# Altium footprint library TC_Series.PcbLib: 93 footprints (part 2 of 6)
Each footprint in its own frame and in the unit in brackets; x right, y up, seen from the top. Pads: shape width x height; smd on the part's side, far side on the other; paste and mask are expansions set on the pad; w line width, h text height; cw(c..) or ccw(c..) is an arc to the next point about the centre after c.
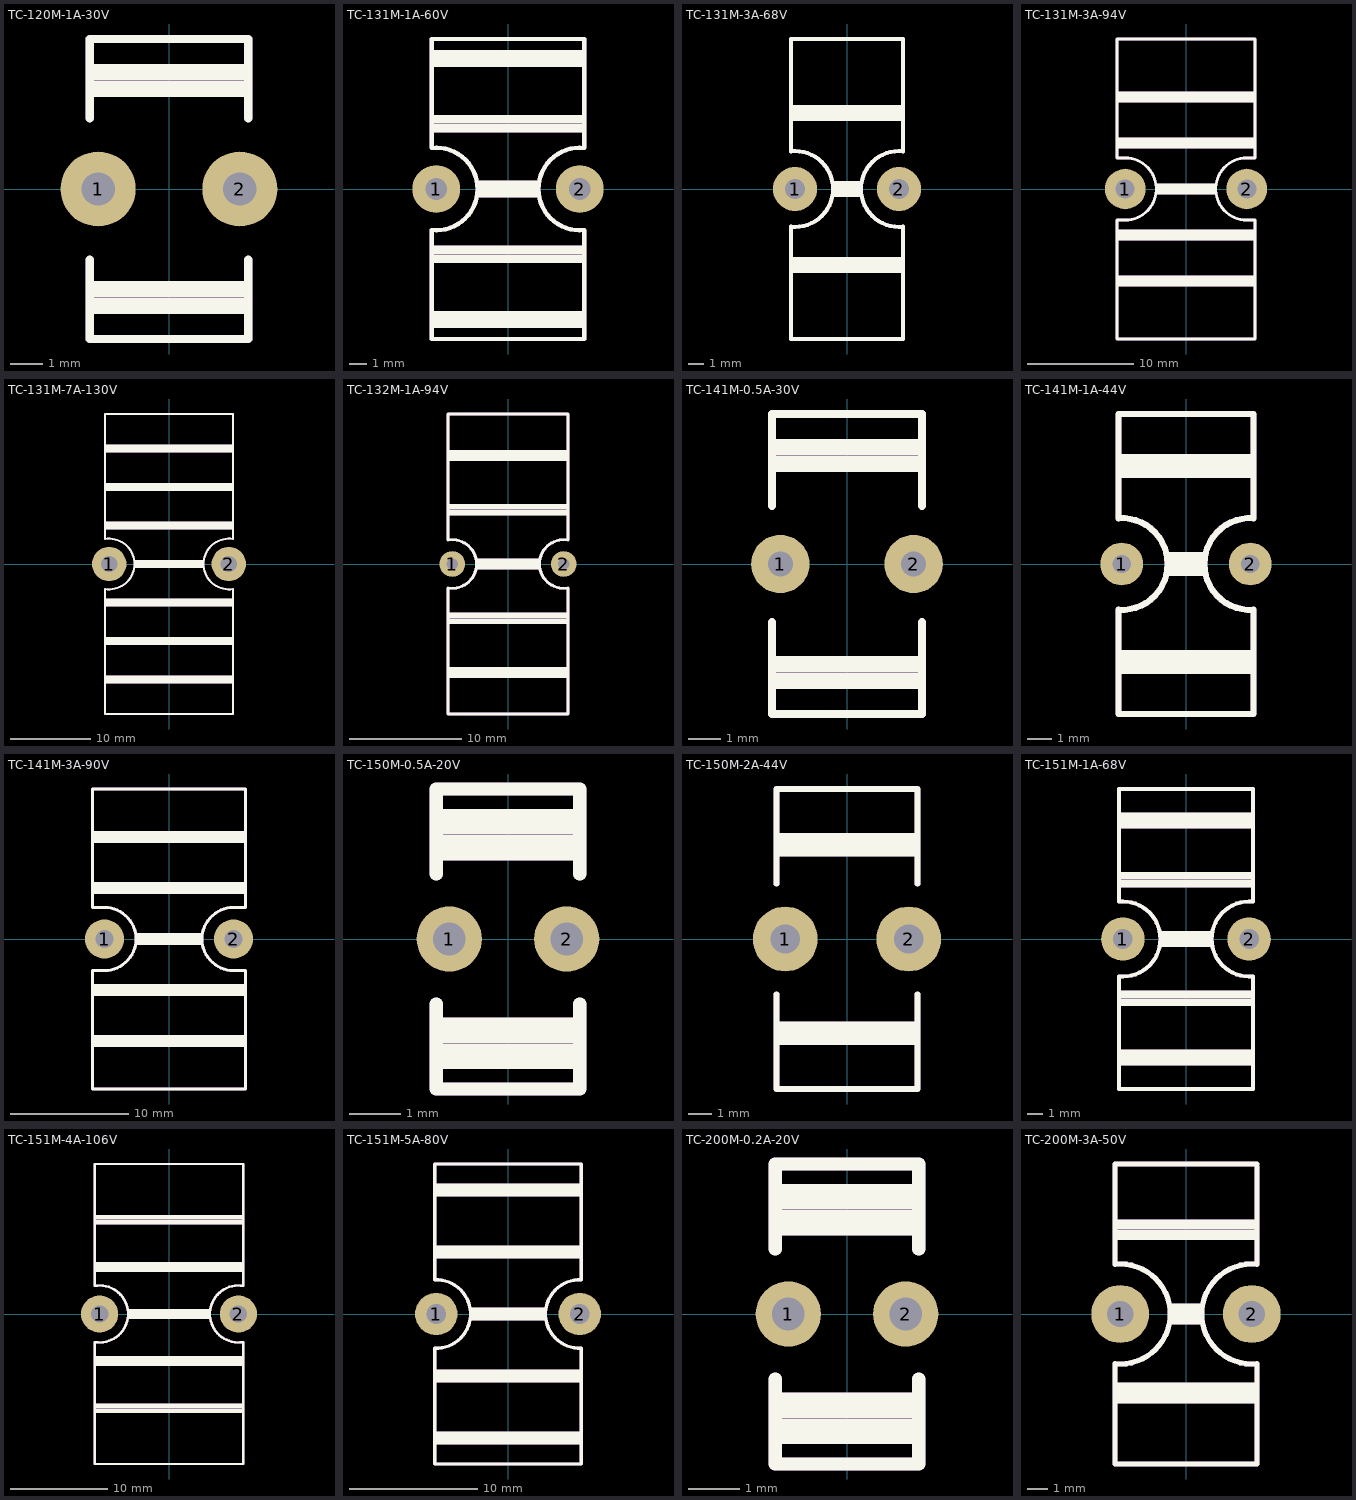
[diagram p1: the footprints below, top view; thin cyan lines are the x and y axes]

## TC-120M-1A-30V [mil]
pads (2):
  round 90 hole 40: 1(-85,0) 2(85,0)
Top Overlay:
  lines w10: -95,-85 -95,-180 95,-180 95,-85 ; -95,85 -95,180 95,180 95,85
  lines w19.68: -90,-140 90,-140 ; -90,-120 90,-120 ; -90,120 90,120 ; -90,140 90,140
Mechanical 29:
  lines w10: -95,-85 -95,-180 95,-180 95,-85 ; -95,85 -95,180 95,180 95,85
  lines w19.68: -90,-140 90,-140 ; -90,-120 90,-120 ; -90,120 90,120 ; -90,140 90,140
  text "'.Designator'" at -800,-62.45 h200

## TC-131M-1A-60V [mil]
pads (2):
  round 110 hole 50: 1(-165,0) 2(165,0)
Top Overlay:
  lines w10: -175,-94.48 -175,-345 175,-345 175,-95 ; -175,-94.47 ccw(c-165,0) -174.95,94.48 ; -175,94.48 -175,345 175,345 175,95 ; 174.95,-94.48 cw(c165,0) 174.93,94.48
  lines w19.68: -170,-310 170,-310 ; -170,-290 170,-290 ; -170,-160 170,-160 ; -170,-140 170,-140 ; -170,140 170,140 ; -170,160 170,160 ; -170,290 170,290 ; -170,310 170,310 ; -65,-10 65,-10 ; -65,10 65,10
Mechanical 29:
  lines w10: -175,-94.48 -175,-345 175,-345 175,-95 ; -175,-94.47 ccw(c-165,0) -174.95,94.48 ; -175,94.48 -175,345 175,345 175,95 ; 174.95,-94.48 cw(c165,0) 174.93,94.48
  lines w19.68: -170,-310 170,-310 ; -170,-290 170,-290 ; -170,-160 170,-160 ; -170,-140 170,-140 ; -170,140 170,140 ; -170,160 170,160 ; -170,290 170,290 ; -170,310 170,310 ; -65,-10 65,-10 ; -65,10 65,10
  text "'.Designator'" at -1750,-64.85 h400

## TC-131M-3A-68V [mil]
pads (2):
  round 110 hole 50: 1(-130,0) 2(130,0)
Top Overlay:
  lines w10: -140,-94.47 ccw(c-130,0) -140,94.47 ; -140,-94.34 -140,-375 140,-375 140,-94.35 ; -140,94.35 -140,375 140,375 140,94.35 ; 140,-94.47 cw(c130,0) 140,94.47
  lines w19.68: -135,-200 135,-200 ; -135,-180 135,-180 ; -135,180 135,180 ; -135,200 135,200 ; -30,-10 30,-10 ; -30,10 30,10
Mechanical 29:
  lines w10: -140,-94.47 ccw(c-130,0) -140,94.47 ; -140,-94.34 -140,-375 140,-375 140,-94.35 ; -140,94.35 -140,375 140,375 140,94.35 ; 140,-94.47 cw(c130,0) 140,94.47
  lines w19.68: -135,-200 135,-200 ; -135,-180 135,-180 ; -135,180 135,180 ; -135,200 135,200 ; -30,-10 30,-10 ; -30,10 30,10
  text "'.Designator'" at -1750,-64.85 h400

## TC-131M-3A-94V [mil]
pads (2):
  round 150 hole 70: 1(-225,0) 2(225,0)
Top Overlay:
  lines w10: -255,-555 255,-555 255,-115 225,-115 cw(c225,0) 225,115 255,115 255,555 -255,555 -255,115 -225,115 cw(c-225,0) -225,-115 -255,-115 -255,-555
  lines w19.68: -250,-350 250,-350 ; -250,-330 250,-330 ; -250,-180 250,-180 ; -250,-160 250,-160 ; -250,160 250,160 ; -250,180 250,180 ; -250,330 250,330 ; -250,350 250,350 ; -105,-10 105,-10 ; -105,10 105,10
Mechanical 29:
  lines w10: -255,-555 255,-555 255,-115 225,-115 cw(c225,0) 225,115 255,115 255,555 -255,555 -255,115 -225,115 cw(c-225,0) -225,-115 -255,-115 -255,-555
  lines w19.68: -250,-350 250,-350 ; -250,-330 250,-330 ; -250,-180 250,-180 ; -250,-160 250,-160 ; -250,160 250,160 ; -250,180 250,180 ; -250,330 250,330 ; -250,350 250,350 ; -105,-10 105,-10 ; -105,10 105,10
  text "'.Designator'" at -1750,-64.85 h400

## TC-131M-7A-130V [mil]
pads (2):
  round 170 hole 80: 1(-295,0) 2(295,0)
Top Overlay:
  lines w10: -315,-740 315,-740 315,-123.39 cw(c295,0) 315,123.39 315,740 -315,740 ; -315,-738.39 -315,-123.39 ccw(c-295,0) -315,123.39 -315,738.39
  lines w19.68: -310,-580 310,-580 ; -310,-560 310,-560 ; -310,-390 310,-390 ; -310,-370 310,-370 ; -310,-200 310,-200 ; -310,-180 310,-180 ; -310,180 310,180 ; -310,200 310,200 ; -310,370 310,370 ; -310,390 310,390 ; -310,560 310,560 ; -310,580 310,580 ; -165,-10 165,-10 ; -165,10 165,10
Mechanical 29:
  lines w10: -315,-740 315,-740 315,-123.39 cw(c295,0) 315,123.39 315,740 -315,740 ; -315,-738.39 -315,-123.39 ccw(c-295,0) -315,123.39 -315,738.39
  lines w19.68: -310,-580 310,-580 ; -310,-560 310,-560 ; -310,-390 310,-390 ; -310,-370 310,-370 ; -310,-200 310,-200 ; -310,-180 310,-180 ; -310,180 310,180 ; -310,200 310,200 ; -310,370 310,370 ; -310,390 310,390 ; -310,560 310,560 ; -310,580 310,580 ; -165,-10 165,-10 ; -165,10 165,10
  text "'.Designator'" at -1750,-64.85 h400

## TC-132M-1A-94V [mil]
pads (2):
  round 90 hole 40: 1(-195,0) 2(195,0)
Top Overlay:
  lines w10: -210,-83.71 -210,-525 210,-525 210,-83.71 ; -210,83.71 -210,525 210,525 210,83.71 ; -209.77,-83.71 ccw(c-195,0) -209.77,83.71 ; 209.77,-83.71 cw(c195,0) 209.77,83.71
  lines w19.68: -205,-390 205,-390 ; -205,-370 205,-370 ; -205,-200 205,-200 ; -205,-180 205,-180 ; -205,180 205,180 ; -205,200 205,200 ; -205,370 205,370 ; -205,390 205,390 ; -105,-10 105,-10 ; -105,10 105,10
Mechanical 29:
  lines w10: -210,-83.71 -210,-525 210,-525 210,-83.71 ; -210,83.71 -210,525 210,525 210,83.71 ; -209.77,-83.71 ccw(c-195,0) -209.77,83.71 ; 209.77,-83.71 cw(c195,0) 209.77,83.71
  lines w19.68: -205,-390 205,-390 ; -205,-370 205,-370 ; -205,-200 205,-200 ; -205,-180 205,-180 ; -205,180 205,180 ; -205,200 205,200 ; -205,370 205,370 ; -205,390 205,390 ; -105,-10 105,-10 ; -105,10 105,10
  text "'.Designator'" at -1750,-64.85 h400

## TC-141M-0.5A-30V [mil]
pads (2):
  round 70 hole 30: 1(-80,0) 2(80,0)
Top Overlay:
  lines w10: -90,-70 -90,-180 90,-180 90,-70 ; -90,70 -90,180 90,180 90,70
  lines w19.68: -85,-140 85,-140 ; -85,-120 85,-120 ; -85,120 85,120 ; -85,140 85,140
Mechanical 29:
  lines w10: -90,-70 -90,-180 90,-180 90,-70 ; -90,70 -90,180 90,180 90,70
  lines w19.68: -85,-140 85,-140 ; -85,-120 85,-120 ; -85,120 85,120 ; -85,140 85,140
  text "'.Designator'" at -805,-37.45 h200

## TC-141M-1A-44V [mil]
pads (2):
  round 70 hole 30: 1(-105,0) 2(105,0)
Top Overlay:
  lines w10: -110,-74.83 ccw(c-105,0) -110,74.83 ; -110,-74.78 -110,-245 110,-245 110,-74.78 ; -110,74.78 -110,245 110,245 110,74.78 ; 110,-74.83 cw(c105,0) 110,74.83
  lines w19.68: -105,-170 105,-170 ; -105,-150 105,-150 ; -105,150 105,150 ; -105,170 105,170 ; -25,-10 25,-10 ; -25,10 25,10
Mechanical 29:
  lines w10: -110,-74.83 ccw(c-105,0) -110,74.83 ; -110,-74.78 -110,-245 110,-245 110,-74.78 ; -110,74.78 -110,245 110,245 110,74.78 ; 110,-74.83 cw(c105,0) 110,74.83
  lines w19.68: -105,-170 105,-170 ; -105,-150 105,-150 ; -105,150 105,150 ; -105,170 105,170 ; -25,-10 25,-10 ; -25,10 25,10
  text "'.Designator'" at -1750,-64.85 h400

## TC-141M-3A-90V [mil]
pads (2):
  round 130 hole 60: 1(-215,0) 2(215,0)
Top Overlay:
  lines w10: -255,-500 255,-500 255,-105 215,-105 cw(c215,0) 215,105 255,105 255,500 -255,500 -255,105 -215,105 cw(c-215,0) -215,-105 -255,-105 -255,-500
  lines w19.68: -250,-350 250,-350 ; -250,-330 250,-330 ; -250,-180 250,-180 ; -250,-160 250,-160 ; -250,160 250,160 ; -250,180 250,180 ; -250,330 250,330 ; -250,350 250,350 ; -105,-10 105,-10 ; -105,10 105,10
Mechanical 29:
  lines w10: -255,-500 255,-500 255,-105 215,-105 cw(c215,0) 215,105 255,105 255,500 -255,500 -255,105 -215,105 cw(c-215,0) -215,-105 -255,-105 -255,-500
  lines w19.68: -250,-350 250,-350 ; -250,-330 250,-330 ; -250,-180 250,-180 ; -250,-160 250,-160 ; -250,160 250,160 ; -250,180 250,180 ; -250,330 250,330 ; -250,350 250,350 ; -105,-10 105,-10 ; -105,10 105,10
  text "'.Designator'" at -1750,-64.85 h400

## TC-150M-0.5A-20V [mil]
pads (2):
  round 50 hole 25: 1(-45,0) 2(45,0)
Top Overlay:
  lines w10: -55,-50 -55,-115 55,-115 55,-50 ; -55,50 -55,115 55,115 55,50
  lines w19.68: -50,-90 50,-90 ; -50,-70 50,-70 ; -50,70 50,70 ; -50,90 50,90
Mechanical 29:
  lines w10: -55,-50 -55,-115 55,-115 55,-50 ; -55,50 -55,115 55,115 55,50
  lines w19.68: -50,-90 50,-90 ; -50,-70 50,-70 ; -50,70 50,70 ; -50,90 50,90
  text "'.Designator'" at -750,-62.45 h200

## TC-150M-2A-44V [mil]
pads (2):
  round 110 hole 50: 1(-105,0) 2(105,0)
Top Overlay:
  lines w10: -120,-93.84 -120,-255 120,-255 120,-93.84 ; -120,93.84 -120,255 120,255 120,93.84
  lines w19.68: -115,-170 115,-170 ; -115,-150 115,-150 ; -115,150 115,150 ; -115,170 115,170
Mechanical 29:
  lines w10: -120,-93.84 -120,-255 120,-255 120,-93.84 ; -120,93.84 -120,255 120,255 120,93.84
  lines w19.68: -115,-170 115,-170 ; -115,-150 115,-150 ; -115,150 115,150 ; -115,170 115,170
  text "'.Designator'" at -755,-52.45 h200

## TC-151M-1A-68V [mil]
pads (2):
  round 110 hole 50: 1(-160,0) 2(160,0)
Top Overlay:
  lines w10: -170,-94.48 -170,-380 170,-380 170,-94.48 ; -170,94.48 -170,380 170,380 170,95 ; -169.95,-94.48 ccw(c-160,0) -169.95,94.48 ; 169.95,-94.48 cw(c160,0) 169.95,94.48
  lines w19.68: -165,-310 165,-310 ; -165,-290 165,-290 ; -165,-160 165,-160 ; -165,-140 165,-140 ; -165,140 165,140 ; -165,160 165,160 ; -165,290 165,290 ; -165,310 165,310 ; -60,-10 60,-10 ; -60,10 60,10
Mechanical 29:
  lines w10: -170,-94.48 -170,-380 170,-380 170,-94.48 ; -170,94.48 -170,380 170,380 170,95 ; -169.95,-94.48 ccw(c-160,0) -169.95,94.48 ; 169.95,-94.48 cw(c160,0) 169.95,94.48
  lines w19.68: -165,-310 165,-310 ; -165,-290 165,-290 ; -165,-160 165,-160 ; -165,-140 165,-140 ; -165,140 165,140 ; -165,160 165,160 ; -165,290 165,290 ; -165,310 165,310 ; -60,-10 60,-10 ; -60,10 60,10
  text "'.Designator'" at -1750,-64.85 h400

## TC-151M-4A-106V [mil]
pads (2):
  round 150 hole 70: 1(-280,0) 2(280,0)
Top Overlay:
  lines w10: -300,-605 300,-605 ; -300,-603.74 -300,-113.39 ; -299.98,113.25 cw(c-280,0) -299.17,-113.39 ; -300,113.39 -300,603.74 ; -300,605 300,605 ; 299.17,-113.39 cw(c280,0) 299.98,113.25 ; 300,-603.63 300,-113.39 ; 300,113.39 300,603.63
  lines w19.68: -295,-390 295,-390 ; -295,-370 295,-370 ; -295,-200 295,-200 ; -295,-180 295,-180 ; -295,180 295,180 ; -295,200 295,200 ; -295,370 295,370 ; -295,390 295,390 ; -160,-10 160,-10 ; -160,10 160,10
Mechanical 29:
  lines w10: -300,-605 300,-605 ; -300,-603.74 -300,-113.39 ; -299.98,113.25 cw(c-280,0) -299.17,-113.39 ; -300,113.39 -300,603.74 ; -300,605 300,605 ; 299.17,-113.39 cw(c280,0) 299.98,113.25 ; 300,-603.63 300,-113.39 ; 300,113.39 300,603.63
  lines w19.68: -295,-390 295,-390 ; -295,-370 295,-370 ; -295,-200 295,-200 ; -295,-180 295,-180 ; -295,180 295,180 ; -295,200 295,200 ; -295,370 295,370 ; -295,390 295,390 ; -160,-10 160,-10 ; -160,10 160,10
  text "'.Designator'" at -1750,-64.85 h400

## TC-151M-5A-80V [mil]
pads (2):
  round 130 hole 60: 1(-220,0) 2(220,0)
Top Overlay:
  lines w10: -225.04,-104.88 ccw(c-220,0) -224.99,104.88 ; -225,-105 -225,-460 225,-460 225,-104.88 cw(c220,0) 225,104.88 225,460 -225,460 -225,105
  lines w19.68: -220,-390 220,-390 ; -220,-370 220,-370 ; -220,-200 220,-200 ; -220,-180 220,-180 ; -220,180 220,180 ; -220,200 220,200 ; -220,370 220,370 ; -220,390 220,390 ; -110,-10 110,-10 ; -110,10 110,10
Mechanical 29:
  lines w10: -225.04,-104.88 ccw(c-220,0) -224.99,104.88 ; -225,-105 -225,-460 225,-460 225,-104.88 cw(c220,0) 225,104.88 225,460 -225,460 -225,105
  lines w19.68: -220,-390 220,-390 ; -220,-370 220,-370 ; -220,-200 220,-200 ; -220,-180 220,-180 ; -220,180 220,180 ; -220,200 220,200 ; -220,370 220,370 ; -220,390 220,390 ; -110,-10 110,-10 ; -110,10 110,10
  text "'.Designator'" at -1750,-64.85 h400

## TC-200M-0.2A-20V [mil]
pads (2):
  round 50 hole 25: 1(-45,0) 2(45,0)
Top Overlay:
  lines w10: -55,-50 -55,-115 55,-115 55,-50 ; -55,50 -55,115 55,115 55,50
  lines w19.68: -50,-90 50,-90 ; -50,-70 50,-70 ; -50,70 50,70 ; -50,90 50,90
Mechanical 29:
  lines w10: -55,-50 -55,-115 55,-115 55,-50 ; -55,50 -55,115 55,115 55,50
  lines w19.68: -50,-90 50,-90 ; -50,-70 50,-70 ; -50,70 50,70 ; -50,90 50,90
  text "'.Designator'" at -850,-42.45 h200

## TC-200M-3A-50V [mil]
pads (2):
  round 110 hole 50: 1(-125,0) 2(125,0)
Top Overlay:
  lines w10: -135,-95 -135,-285 135,-285 135,-95 ; -135,95 -135,285 135,285 ; -134.95,-94.48 ccw(c-125,0) -134.95,94.48 ; 134.95,-94.48 cw(c125,0) 134.95,94.48 ; 135,95 135,279.87
  lines w19.68: -130,-160 130,-160 ; -130,-140 130,-140 ; -130,150 130,150 ; -130,170 130,170 ; -25,-10 25,-10 ; -25,10 25,10
Mechanical 29:
  lines w10: -135,-95 -135,-285 135,-285 135,-95 ; -135,95 -135,285 135,285 ; -134.95,-94.48 ccw(c-125,0) -134.95,94.48 ; 134.95,-94.48 cw(c125,0) 134.95,94.48 ; 135,95 135,279.87
  lines w19.68: -130,-160 130,-160 ; -130,-140 130,-140 ; -130,150 130,150 ; -130,170 130,170 ; -25,-10 25,-10 ; -25,10 25,10
  text "'.Designator'" at -1750,-64.85 h400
